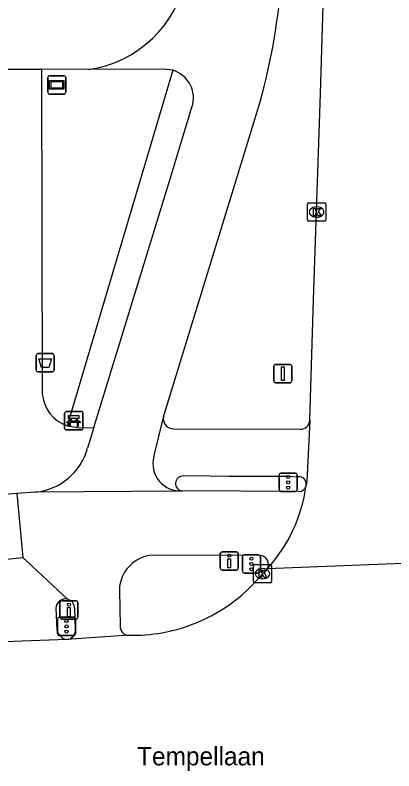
# Model space of a CAD drawing. Extents: x 160457 to 162082, y 388340 to 389736.
# Drawn here: x 161012.2 to 161032.93, y 388343.98 to 388385.31 of the extents above; entities that cross this region are included whole.
import ezdxf

# ---------------------------------------------------------------- set-up
doc = ezdxf.new("R2010")
doc.units = 0
for name, color, linetype in [('IMGEO_Afvalbak', 7, 'Continuous'), ('IMGEO_Bank', 7, 'Continuous'), ('IMGEO_Drukknoppaal', 7, 'Continuous'), ('IMGEO_Fietspad_gesloten', 7, 'Continuous'), ('IMGEO_Fietspad_open', 7, 'Continuous'), ('IMGEO_Haag', 7, 'Continuous'), ('IMGEO_Kolk', 7, 'Continuous'), ('IMGEO_Openbare_ruimte_label', 7, 'Continuous'), ('IMGEO_Rijbaan_lokaal_gesloten', 7, 'Continuous'), ('IMGEO_Rijbaan_lokaal_open', 7, 'Continuous'), ('IMGEO_Rijbaan_regionaal_gesloten', 7, 'Continuous'), ('IMGEO_Straatnaambord', 7, 'Continuous'), ('IMGEO_Verkeersbordpaal', 7, 'Continuous'), ('IMGEO_Verkeersregelinstallatiepaal', 7, 'Continuous'), ('IMGEO_Voetpad_open', 7, 'Continuous')]:
    doc.layers.add(name, color=color, linetype=linetype)

msp = doc.modelspace()

# ---------------------------------------------------------------- linework, layer by layer
at = {"layer": 'IMGEO_Afvalbak'}
for p, q in [((161013.344, 388365.898), (161013.344, 388366.698)), ((161013.344, 388366.698), (161013.344, 388365.898)), ((161013.444, 388366.798), (161014.234, 388366.798)), ((161014.234, 388366.798), (161013.444, 388366.798)), ((161014.334, 388366.698), (161014.334, 388365.898)), ((161014.334, 388365.898), (161014.334, 388366.698)), ((161014.234, 388365.798), (161013.444, 388365.798)), ((161013.444, 388365.798), (161014.234, 388365.798))]:
    msp.add_line(p, q, dxfattribs=at)
msp.add_lwpolyline([(161013.487, 388366.512), (161014.191, 388366.512), (161014.042, 388366.042), (161013.636, 388366.042), (161013.487, 388366.512)], dxfattribs=at)
for centre, start, end in [((161013.444, 388366.698), 90, 180), ((161013.444, 388366.698), 90, 180), ((161014.234, 388366.698), 0, 90), ((161014.234, 388366.698), 360, 90), ((161013.444, 388365.898), 180, 270), ((161013.444, 388365.898), 180, 270), ((161014.234, 388365.898), 270, 0), ((161014.234, 388365.898), 270, 0)]:
    msp.add_arc(centre, 0.1, start, end, dxfattribs=at)
at = {"layer": 'IMGEO_Bank'}
for p, q in [((161014.907, 388362.703), (161014.907, 388363.544)), ((161014.907, 388363.544), (161014.907, 388362.703)), ((161014.982, 388363.628), (161015.823, 388363.628)), ((161015.823, 388363.628), (161014.982, 388363.628)), ((161015.907, 388363.553), (161015.907, 388362.712)), ((161015.907, 388362.712), (161015.907, 388363.553)), ((161015.216, 388363.134), (161015.216, 388363.24)), ((161015.26, 388363.24), (161015.26, 388363.134)), ((161015.548, 388363.246), (161015.266, 388363.246)), ((161015.266, 388363.128), (161015.548, 388363.128)), ((161015.554, 388363.134), (161015.554, 388363.24)), ((161015.598, 388363.24), (161015.598, 388363.134)), ((161015.604, 388363.026), (161015.211, 388363.026)), ((161015.832, 388362.628), (161014.991, 388362.628)), ((161014.991, 388362.628), (161015.832, 388362.628))]:
    msp.add_line(p, q, dxfattribs=at)
for points in [[(161015.154, 388363.026), (161015.012, 388363.026), (161015.124, 388363.128), (161015.21, 388363.128)], [(161015.21, 388363.246), (161015.124, 388363.246), (161015.124, 388363.407), (161015.687, 388363.407), (161015.687, 388363.246), (161015.604, 388363.246)], [(161015.604, 388363.128), (161015.687, 388363.128), (161015.799, 388363.026), (161015.66, 388363.026)], [(161015.204, 388363.019), (161015.204, 388362.812), (161015.161, 388362.812), (161015.161, 388363.019)], [(161015.654, 388363.019), (161015.654, 388362.812), (161015.61, 388362.812), (161015.61, 388363.019)]]:
    msp.add_lwpolyline(points, dxfattribs=at)
for centre, radius, start, end in [((161014.985, 388363.55), 0.0779, 92.4484, 184.2845), ((161014.985, 388363.55), 0.0779, 92.4484, 184.2845), ((161015.829, 388363.55), 0.0779, 2.4484, 94.2845), ((161015.829, 388363.55), 0.0779, 2.4484, 94.2845), ((161015.209, 388363.239), 0.00671, 2.8957, 87.1043), ((161015.209, 388363.135), 0.00671, 272.8957, 357.1043), ((161015.266, 388363.239), 0.00671, 92.8957, 177.1043), ((161015.266, 388363.135), 0.00671, 182.8957, 267.1043), ((161015.548, 388363.239), 0.00671, 2.8957, 87.1043), ((161015.548, 388363.135), 0.00671, 272.8957, 357.1043), ((161015.605, 388363.239), 0.00671, 92.8957, 177.1043), ((161015.605, 388363.135), 0.00671, 182.8957, 267.1043), ((161014.985, 388362.706), 0.0779, 182.4484, 274.2845), ((161014.985, 388362.706), 0.0779, 182.4484, 274.2845), ((161015.154, 388363.019), 0.00671, 2.8957, 87.1043), ((161015.211, 388363.019), 0.00671, 92.8957, 177.1043), ((161015.603, 388363.019), 0.00671, 2.8957, 87.1043), ((161015.66, 388363.019), 0.00671, 92.8957, 177.1043), ((161015.829, 388362.706), 0.0779, 272.4484, 4.2845), ((161015.829, 388362.706), 0.0779, 272.4484, 4.2845)]:
    msp.add_arc(centre, radius, start, end, dxfattribs=at)
at = {"layer": 'IMGEO_Drukknoppaal'}
for p, q in [((161023.424, 388355.058), (161023.424, 388355.858)), ((161023.424, 388355.858), (161023.424, 388355.058)), ((161023.524, 388355.958), (161024.314, 388355.958)), ((161024.314, 388355.958), (161023.524, 388355.958)), ((161024.414, 388355.858), (161024.414, 388355.058)), ((161024.414, 388355.058), (161024.414, 388355.858)), ((161024.314, 388354.958), (161023.524, 388354.958)), ((161023.524, 388354.958), (161024.314, 388354.958)), ((161014.647, 388352.382), (161014.647, 388353.182)), ((161014.647, 388353.182), (161014.647, 388352.382)), ((161014.747, 388353.282), (161015.537, 388353.282)), ((161015.537, 388353.282), (161014.747, 388353.282)), ((161015.637, 388353.182), (161015.637, 388352.382)), ((161015.637, 388352.382), (161015.637, 388353.182)), ((161015.537, 388352.282), (161014.747, 388352.282)), ((161014.747, 388352.282), (161015.537, 388352.282))]:
    msp.add_line(p, q, dxfattribs=at)
for points in [[(161023.994, 388355.583), (161023.994, 388355.083), (161023.844, 388355.083), (161023.844, 388355.583), (161023.994, 388355.583)], [(161015.217, 388352.907), (161015.217, 388352.407), (161015.067, 388352.407), (161015.067, 388352.907), (161015.217, 388352.907)]]:
    msp.add_lwpolyline(points, dxfattribs=at)
for centre in [(161023.919, 388355.748), (161015.142, 388353.072)]:
    msp.add_circle(centre, 0.085, dxfattribs=at)
for centre, start, end in [((161023.524, 388355.858), 90, 180), ((161023.524, 388355.858), 90, 180), ((161024.314, 388355.858), 0, 90), ((161024.314, 388355.858), 360, 90), ((161023.524, 388355.058), 180, 270), ((161023.524, 388355.058), 180, 270), ((161024.314, 388355.058), 270, 0), ((161024.314, 388355.058), 270, 0), ((161014.747, 388353.182), 90, 180), ((161014.747, 388353.182), 90, 180), ((161015.537, 388353.182), 0, 90), ((161015.537, 388353.182), 360, 90), ((161014.747, 388352.382), 180, 270), ((161014.747, 388352.382), 180, 270), ((161015.537, 388352.382), 270, 0), ((161015.537, 388352.382), 270, 0)]:
    msp.add_arc(centre, 0.1, start, end, dxfattribs=at)
at = {"layer": 'IMGEO_Fietspad_gesloten'}
for points in [[(161012.297, 388359.142), (161000, 388358.164), (160954.457, 388354.688)], [(161012.297, 388359.142), (161012.618, 388355.65)], [(161011.548, 388355.547), (161012.618, 388355.65)]]:
    msp.add_lwpolyline(points, dxfattribs=at)
at = {"layer": 'IMGEO_Fietspad_open'}
for points in [[(161020.825, 388382.291), (161020.31, 388382.351), (161016.228, 388382.343)], [(161020.318, 388363.346), (161024.579, 388377.185), (161025.607, 388380.563)], [(161016.51, 388362.755), (161020.686, 388376.364), (161021.875, 388380.275)], [(161019.788, 388361.159), (161020.282, 388363.16), (161020.309, 388363.252)], [(161016.51, 388362.755), (161016.159, 388361.626)], [(161013.315, 388359.221), (161012.297, 388359.142)], [(161021.349, 388359.289), (161021.228, 388359.276), (161013.315, 388359.221)], [(161027.726, 388359.254), (161021.349, 388359.289)], [(161025.622, 388355.76), (161019.732, 388355.783)], [(161012.618, 388355.65), (161015.064, 388353.364)], [(161017.903, 388353.866), (161017.949, 388351.9)], [(161015.504, 388351.695), (161015.456, 388352.901)]]:
    msp.add_lwpolyline(points, dxfattribs=at)
for centre, radius, start, end in [((160991.032, 388390.109), 35.868, 344.5652, 355.7934), ((161020.387, 388380.782), 1.571, 341.1904, 73.8336), ((161021.056, 388363.228), 0.747, 170.9081, 178.1537), ((161012.984, 388362.497), 3.293, 275.7779, 344.6605), ((161021.237, 388360.782), 1.497, 165.4205, 274.287), ((161027.748, 388359.64), 0.387, 266.6754, 351.331), ((161019.88, 388353.811), 1.978, 94.2911, 178.4004), ((161025.572, 388355.268), 0.494, 329.9325, 84.2471), ((161014.943, 388352.864), 0.514, 4.0899, 76.4161), ((161014.995, 388351.675), 0.51, 274.3269, 2.2043), ((161018.416, 388351.866), 0.468, 175.7966, 270.796)]:
    msp.add_arc(centre, radius, start, end, dxfattribs=at)
at = {"layer": 'IMGEO_Haag'}
msp.add_lwpolyline([(161020.825, 388382.291), (161015.044, 388362.85)], dxfattribs=at)
at = {"layer": 'IMGEO_Kolk'}
for p, q in [((161028.201, 388374.113), (161028.201, 388374.965)), ((161028.276, 388375.039), (161029.128, 388375.039)), ((161028.689, 388374.819), (161028.714, 388374.819)), ((161029.202, 388374.965), (161029.202, 388374.113)), ((161028.712, 388374.259), (161028.687, 388374.259)), ((161029.128, 388374.039), (161028.276, 388374.039)), ((161025.314, 388355.263), (161026.166, 388355.263)), ((161025.239, 388354.337), (161025.239, 388355.189)), ((161025.727, 388355.043), (161025.752, 388355.043)), ((161026.24, 388355.189), (161026.24, 388354.337)), ((161025.75, 388354.483), (161025.725, 388354.483)), ((161026.166, 388354.263), (161025.314, 388354.263))]:
    msp.add_line(p, q, dxfattribs=at)
for points in [[(161028.201, 388374.113), (161028.201, 388374.965)], [(161028.276, 388375.039), (161029.128, 388375.039)], [(161028.522, 388374.739), (161028.645, 388374.739), (161028.645, 388374.588), (161028.775, 388374.739), (161028.939, 388374.739), (161028.793, 388374.588), (161028.946, 388374.339), (161028.794, 388374.339), (161028.709, 388374.503), (161028.645, 388374.436), (161028.645, 388374.339), (161028.522, 388374.339), (161028.522, 388374.739)], [(161029.202, 388374.965), (161029.202, 388374.113)], [(161029.128, 388374.039), (161028.276, 388374.039)], [(161025.314, 388355.263), (161026.166, 388355.263)], [(161025.239, 388354.337), (161025.239, 388355.189)], [(161025.56, 388354.963), (161025.683, 388354.963), (161025.683, 388354.812), (161025.813, 388354.963), (161025.977, 388354.963), (161025.831, 388354.812), (161025.984, 388354.563), (161025.832, 388354.563), (161025.747, 388354.727), (161025.683, 388354.66), (161025.683, 388354.563), (161025.56, 388354.563), (161025.56, 388354.963)], [(161026.24, 388355.189), (161026.24, 388354.337)], [(161026.166, 388354.263), (161025.314, 388354.263)]]:
    msp.add_lwpolyline(points, dxfattribs=at)
for centre, start, end in [((161028.278, 388374.963), 91.552, 178.448), ((161028.278, 388374.963), 91.552, 178.448), ((161029.126, 388374.963), 1.552, 88.448), ((161029.126, 388374.963), 1.552, 88.448), ((161028.278, 388374.115), 181.552, 268.448), ((161028.278, 388374.115), 181.552, 268.448), ((161029.126, 388374.115), 271.552, 358.448), ((161029.126, 388374.115), 271.552, 358.448), ((161025.316, 388355.187), 91.552, 178.448), ((161025.316, 388355.187), 91.552, 178.448), ((161026.164, 388355.187), 1.552, 88.448), ((161026.164, 388355.187), 1.552, 88.448), ((161025.316, 388354.339), 181.552, 268.448), ((161025.316, 388354.339), 181.552, 268.448), ((161026.164, 388354.339), 271.552, 358.448), ((161026.164, 388354.339), 271.552, 358.448)]:
    msp.add_arc(centre, 0.0765, start, end, dxfattribs=at)
for centre, major_axis, ratio, start_param, end_param in [((161028.688, 388374.539), (-0.387, 0.002), 0.722429, 4.712389, 7.853982), ((161028.713, 388374.539), (-0.39, 0.002), 0.717154, 1.570796, 4.712389), ((161025.726, 388354.763), (-0.387, 0.002), 0.722429, 4.712389, 7.853982), ((161025.751, 388354.763), (-0.39, 0.002), 0.717154, 1.570796, 4.712389)]:
    msp.add_ellipse(centre, major_axis=major_axis, ratio=ratio, start_param=start_param, end_param=end_param, dxfattribs=at)
at = {"layer": 'IMGEO_Rijbaan_lokaal_gesloten'}
for points in [[(161028.334, 388363.151), (161028.523, 388369.747), (161028.905, 388381.025), (161029.193, 388390.038), (161031.295, 388453.541)], [(161028.334, 388363.151), (161028.158, 388359.809), (161028.136, 388359.622)], [(161028.136, 388359.622), (161028.131, 388359.582)]]:
    msp.add_lwpolyline(points, dxfattribs=at)
msp.add_arc((161019.652, 388360.765), 8.561, 317.8575, 352.0564, dxfattribs=at)
at = {"layer": 'IMGEO_Rijbaan_lokaal_open'}
for points in [[(161011.529, 388382.357), (161013.643, 388382.351)], [(161016.228, 388382.343), (161013.643, 388382.351)]]:
    msp.add_lwpolyline(points, dxfattribs=at)
msp.add_arc((161015.364, 388388.582), 6.298, 277.8894, 349.7423, dxfattribs=at)
at = {"layer": 'IMGEO_Rijbaan_regionaal_gesloten'}
for points in [[(161034.358, 388355.363), (161026, 388355.021)], [(161026, 388355.021), (161025.74, 388354.763)], [(161015.033, 388351.167), (161011.621, 388351.037)], [(161018.422, 388351.398), (161015.033, 388351.167)]]:
    msp.add_lwpolyline(points, dxfattribs=at)
for centre, radius, start, end in [((161018.662, 388360.517), 9.121, 279.9981, 320.8902), ((161018.661, 388360.49), 9.095, 268.4932, 280.0351)]:
    msp.add_arc(centre, radius, start, end, dxfattribs=at)
at = {"layer": 'IMGEO_Straatnaambord'}
for p, q in [((161013.983, 388381.094), (161013.983, 388381.894)), ((161013.983, 388381.894), (161013.983, 388381.094)), ((161014.083, 388381.994), (161014.873, 388381.994)), ((161014.873, 388381.994), (161014.083, 388381.994)), ((161014.973, 388381.894), (161014.973, 388381.094)), ((161014.973, 388381.094), (161014.973, 388381.894)), ((161014.873, 388380.994), (161014.083, 388380.994)), ((161014.083, 388380.994), (161014.873, 388380.994))]:
    msp.add_line(p, q, dxfattribs=at)
for points in [[(161014.084, 388381.726), (161014.872, 388381.726), (161014.872, 388381.262), (161014.084, 388381.262), (161014.084, 388381.726)], [(161014.149, 388381.661), (161014.149, 388381.327), (161014.807, 388381.327), (161014.807, 388381.661), (161014.149, 388381.661)]]:
    msp.add_lwpolyline(points, dxfattribs=at)
for centre, start, end in [((161014.083, 388381.894), 90, 180), ((161014.083, 388381.894), 90, 180), ((161014.873, 388381.894), 0, 90), ((161014.873, 388381.894), 360, 90), ((161014.083, 388381.094), 180, 270), ((161014.083, 388381.094), 180, 270), ((161014.873, 388381.094), 270, 0), ((161014.873, 388381.094), 270, 0)]:
    msp.add_arc(centre, 0.1, start, end, dxfattribs=at)
at = {"layer": 'IMGEO_Verkeersbordpaal'}
for p, q in [((161026.355, 388365.306), (161026.355, 388366.106)), ((161026.355, 388366.106), (161026.355, 388365.306)), ((161026.455, 388366.206), (161027.245, 388366.206)), ((161027.245, 388366.206), (161026.455, 388366.206)), ((161027.345, 388366.106), (161027.345, 388365.306)), ((161027.345, 388365.306), (161027.345, 388366.106)), ((161027.245, 388365.206), (161026.455, 388365.206)), ((161026.455, 388365.206), (161027.245, 388365.206))]:
    msp.add_line(p, q, dxfattribs=at)
msp.add_lwpolyline([(161026.775, 388366.081), (161026.925, 388366.081), (161026.925, 388365.331), (161026.775, 388365.331), (161026.775, 388366.081)], dxfattribs=at)
for centre, start, end in [((161026.455, 388366.106), 90, 180), ((161026.455, 388366.106), 90, 180), ((161027.245, 388366.106), 0, 90), ((161027.245, 388366.106), 360, 90), ((161026.455, 388365.306), 180, 270), ((161026.455, 388365.306), 180, 270), ((161027.245, 388365.306), 270, 0), ((161027.245, 388365.306), 270, 0)]:
    msp.add_arc(centre, 0.1, start, end, dxfattribs=at)
at = {"layer": 'IMGEO_Verkeersregelinstallatiepaal'}
for p, q in [((161026.75, 388360.262), (161027.54, 388360.262)), ((161027.54, 388360.262), (161026.75, 388360.262)), ((161026.65, 388359.362), (161026.65, 388360.162)), ((161026.65, 388360.162), (161026.65, 388359.362)), ((161027.64, 388360.162), (161027.64, 388359.362)), ((161027.64, 388359.362), (161027.64, 388360.162)), ((161027.54, 388359.262), (161026.75, 388359.262)), ((161026.75, 388359.262), (161027.54, 388359.262)), ((161024.638, 388354.894), (161024.638, 388355.694)), ((161024.638, 388355.694), (161024.638, 388354.894)), ((161024.738, 388355.794), (161025.528, 388355.794)), ((161025.528, 388355.794), (161024.738, 388355.794)), ((161025.628, 388355.694), (161025.628, 388354.894)), ((161025.628, 388354.894), (161025.628, 388355.694)), ((161025.528, 388354.794), (161024.738, 388354.794)), ((161024.738, 388354.794), (161025.528, 388354.794)), ((161014.614, 388352.383), (161015.404, 388352.383)), ((161015.404, 388352.383), (161014.614, 388352.383)), ((161014.514, 388351.483), (161014.514, 388352.283)), ((161014.514, 388352.283), (161014.514, 388351.483)), ((161015.504, 388352.283), (161015.504, 388351.483)), ((161015.504, 388351.483), (161015.504, 388352.283)), ((161015.404, 388351.383), (161014.614, 388351.383)), ((161014.614, 388351.383), (161015.404, 388351.383))]:
    msp.add_line(p, q, dxfattribs=at)
for centre in [(161027.145, 388360.052), (161027.145, 388359.762), (161027.145, 388359.472), (161025.133, 388355.584), (161025.133, 388355.294), (161025.133, 388355.004), (161015.009, 388352.173), (161015.009, 388351.883), (161015.009, 388351.593)]:
    msp.add_circle(centre, 0.085, dxfattribs=at)
for centre, start, end in [((161026.75, 388360.162), 90, 180), ((161026.75, 388360.162), 90, 180), ((161027.54, 388360.162), 0, 90), ((161027.54, 388360.162), 360, 90), ((161026.75, 388359.362), 180, 270), ((161026.75, 388359.362), 180, 270), ((161027.54, 388359.362), 270, 0), ((161027.54, 388359.362), 270, 0), ((161024.738, 388355.694), 90, 180), ((161024.738, 388355.694), 90, 180), ((161025.528, 388355.694), 0, 90), ((161025.528, 388355.694), 360, 90), ((161024.738, 388354.894), 180, 270), ((161024.738, 388354.894), 180, 270), ((161025.528, 388354.894), 270, 0), ((161025.528, 388354.894), 270, 0), ((161014.614, 388352.283), 90, 180), ((161014.614, 388352.283), 90, 180), ((161015.404, 388352.283), 0, 90), ((161015.404, 388352.283), 360, 90), ((161014.614, 388351.483), 180, 270), ((161014.614, 388351.483), 180, 270), ((161015.404, 388351.483), 270, 0), ((161015.404, 388351.483), 270, 0)]:
    msp.add_arc(centre, 0.1, start, end, dxfattribs=at)
at = {"layer": 'IMGEO_Voetpad_open'}
for points in [[(161013.643, 388382.351), (161013.685, 388364.613)], [(161015.044, 388362.85), (161015.735, 388362.743), (161016.51, 388362.755)], [(161020.851, 388362.678), (161027.808, 388362.663)], [(161021.41, 388360.107), (161021.721, 388360.125), (161022.85, 388360.113), (161023.899, 388360.103), (161025.417, 388360.103), (161027.091, 388360.103), (161027.7, 388360.068)], [(161014.429, 388352.872), (161014.488, 388351.687)]]:
    msp.add_lwpolyline(points, dxfattribs=at)
for centre, radius, start, end in [((161015.696, 388364.758), 2.016, 184.1122, 251.1411), ((161020.88, 388363.249), 0.571, 179.6721, 267.043), ((161027.813, 388363.185), 0.522, 269.4038, 356.3038), ((161021.389, 388359.697), 0.41, 87.1006, 264.3698), ((161027.726, 388359.657), 0.412, 355.1308, 93.57), ((161014.944, 388352.864), 0.515, 76.4589, 179.0784), ((161015.117, 388351.801), 0.639, 190.2493, 262.4402)]:
    msp.add_arc(centre, radius, start, end, dxfattribs=at)

# ---------------------------------------------------------------- texts
at = {"layer": 'IMGEO_Openbare_ruimte_label'}
msp.add_text('Tempellaan', height=1, dxfattribs=at).set_placement((161018.873, 388344.28))

doc.saveas('drawing.dxf')
